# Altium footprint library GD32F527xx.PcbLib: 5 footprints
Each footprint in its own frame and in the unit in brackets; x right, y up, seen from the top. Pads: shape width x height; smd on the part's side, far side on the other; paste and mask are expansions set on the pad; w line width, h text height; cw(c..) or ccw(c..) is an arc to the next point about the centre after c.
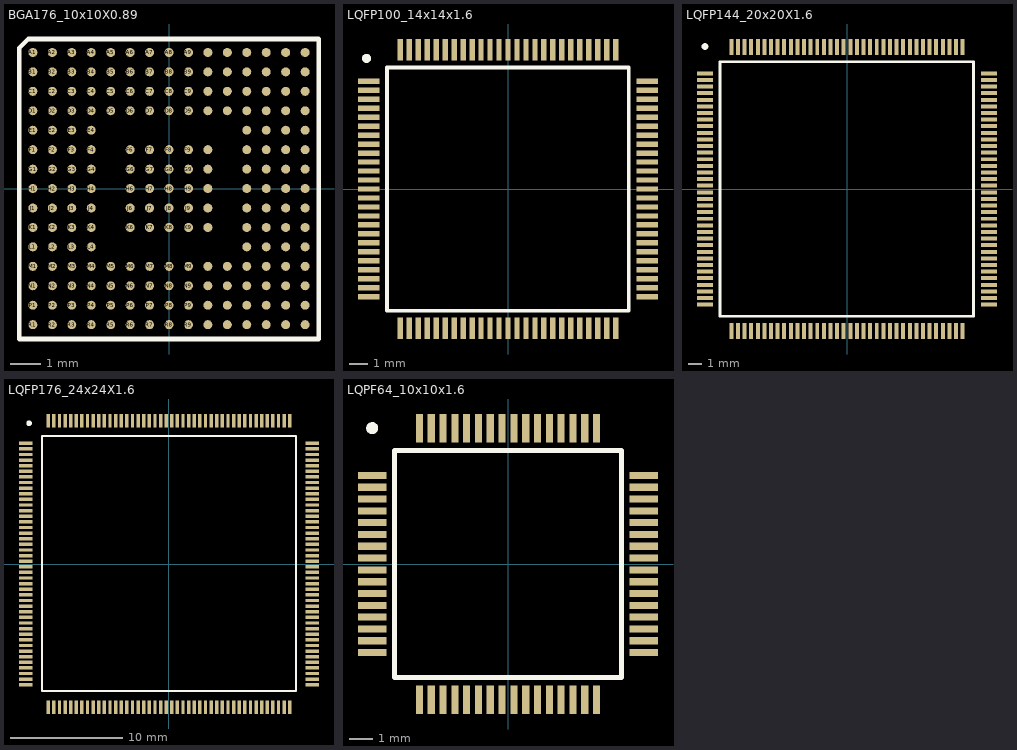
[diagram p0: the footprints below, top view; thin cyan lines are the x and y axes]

## BGA176_10x10X0.89 [mm]
pads (201):
  round 0.3 smd mask+0.05: A1(-4.55,4.55) A2(-3.9,4.55) A3(-3.25,4.55) A4(-2.6,4.55) A5(-1.95,4.55) A6(-1.3,4.55) A7(-0.65,4.55) A8(0,4.55) A9(0.65,4.55) A10(1.3,4.55) A11(1.95,4.55) A12(2.6,4.55) A13(3.25,4.55) A14(3.9,4.55) A15(4.55,4.55) B1(-4.55,3.9) B2(-3.9,3.9) B3(-3.25,3.9) B4(-2.6,3.9) B5(-1.95,3.9) B6(-1.3,3.9) B7(-0.65,3.9) B8(0,3.9) B9(0.65,3.9) B10(1.3,3.9) B11(1.95,3.9) B12(2.6,3.9) B13(3.25,3.9) B14(3.9,3.9) B15(4.55,3.9) C1(-4.55,3.25) C2(-3.9,3.25) C3(-3.25,3.25) C4(-2.6,3.25) C5(-1.95,3.25) C6(-1.3,3.25) C7(-0.65,3.25) C8(0,3.25) C9(0.65,3.25) C10(1.3,3.25) C11(1.95,3.25) C12(2.6,3.25) C13(3.25,3.25) C14(3.9,3.25) C15(4.55,3.25) D1(-4.55,2.6) D2(-3.9,2.6) D3(-3.25,2.6) D4(-2.6,2.6) D5(-1.95,2.6) D6(-1.3,2.6) D7(-0.65,2.6) D8(0,2.6) D9(0.65,2.6) D10(1.3,2.6) D11(1.95,2.6) D12(2.6,2.6) D13(3.25,2.6) D14(3.9,2.6) D15(4.55,2.6) E1(-4.55,1.95) E2(-3.9,1.95) E3(-3.25,1.95) E4(-2.6,1.95) E12(2.6,1.95) E13(3.25,1.95) E14(3.9,1.95) E15(4.55,1.95) F1(-4.55,1.3) F2(-3.9,1.3) F3(-3.25,1.3) F4(-2.6,1.3) F6(-1.3,1.3) F7(-0.65,1.3) F8(0,1.3) F9(0.65,1.3) F10(1.3,1.3) F12(2.6,1.3) F13(3.25,1.3) F14(3.9,1.3) F15(4.55,1.3) G1(-4.55,0.65) G2(-3.9,0.65) G3(-3.25,0.65) G4(-2.6,0.65) G6(-1.3,0.65) G7(-0.65,0.65) G8(0,0.65) G9(0.65,0.65) G10(1.3,0.65) G12(2.6,0.65) G13(3.25,0.65) G14(3.9,0.65) G15(4.55,0.65) H1(-4.55,0) H2(-3.9,0) H3(-3.25,0) H4(-2.6,0) H6(-1.3,0) H7(-0.65,0) H8(0,0) H9(0.65,0) H10(1.3,0) H12(2.6,0) H13(3.25,0) H14(3.9,0) H15(4.55,0) J1(-4.55,-0.65) J2(-3.9,-0.65) J3(-3.25,-0.65) J4(-2.6,-0.65) J6(-1.3,-0.65) J7(-0.65,-0.65) J8(0,-0.65) J9(0.65,-0.65) J10(1.3,-0.65) J12(2.6,-0.65) J13(3.25,-0.65) J14(3.9,-0.65) J15(4.55,-0.65) K1(-4.55,-1.3) K2(-3.9,-1.3) K3(-3.25,-1.3) K4(-2.6,-1.3) K6(-1.3,-1.3) K7(-0.65,-1.3) K8(0,-1.3) K9(0.65,-1.3) K10(1.3,-1.3) K12(2.6,-1.3) K13(3.25,-1.3) K14(3.9,-1.3) K15(4.55,-1.3) L1(-4.55,-1.95) L2(-3.9,-1.95) L3(-3.25,-1.95) L4(-2.6,-1.95) L12(2.6,-1.95) L13(3.25,-1.95) L14(3.9,-1.95) L15(4.55,-1.95) M1(-4.55,-2.6) M2(-3.9,-2.6) M3(-3.25,-2.6) M4(-2.6,-2.6) M5(-1.95,-2.6) M6(-1.3,-2.6) M7(-0.65,-2.6) M8(0,-2.6) M9(0.65,-2.6) M10(1.3,-2.6) M11(1.95,-2.6) M12(2.6,-2.6) M13(3.25,-2.6) M14(3.9,-2.6) M15(4.55,-2.6) N1(-4.55,-3.25) N2(-3.9,-3.25) N3(-3.25,-3.25) N4(-2.6,-3.25) N5(-1.95,-3.25) N6(-1.3,-3.25) N7(-0.65,-3.25) N8(0,-3.25) N9(0.65,-3.25) N10(1.3,-3.25) N11(1.95,-3.25) N12(2.6,-3.25) N13(3.25,-3.25) N14(3.9,-3.25) N15(4.55,-3.25) P1(-4.55,-3.9) P2(-3.9,-3.9) P3(-3.25,-3.9) P4(-2.6,-3.9) P5(-1.95,-3.9) P6(-1.3,-3.9) P7(-0.65,-3.9) P8(0,-3.9) P9(0.65,-3.9) P10(1.3,-3.9) P11(1.95,-3.9) P12(2.6,-3.9) P13(3.25,-3.9) P14(3.9,-3.9) P15(4.55,-3.9) R1(-4.55,-4.55) R2(-3.9,-4.55) R3(-3.25,-4.55) R4(-2.6,-4.55) R5(-1.95,-4.55) R6(-1.3,-4.55) R7(-0.65,-4.55) R8(0,-4.55) R9(0.65,-4.55) R10(1.3,-4.55) R11(1.95,-4.55) R12(2.6,-4.55) R13(3.25,-4.55) R14(3.9,-4.55) R15(4.55,-4.55)
Top Overlay:
  lines w0.152: -5.004,-5.029 5.004,-5.029 5.004,5 -4.703,5 -5.004,4.699 -5.004,-5.029
3D body "BGA176C65P15X15_1000X1000X89.step": height 0.89, standoff 0, extent -5,-5 5,5

## LQFP100_14x14x1.6 [mm]
pads (100):
  rect 1.2x0.3 smd: 1(-7.75,6) 2(-7.75,5.5) 3(-7.75,5) 4(-7.75,4.5) 5(-7.75,4) 6(-7.75,3.5) 7(-7.75,3) 8(-7.75,2.5) 9(-7.75,2) 10(-7.75,1.5) 11(-7.75,1) 12(-7.75,0.5) 13(-7.75,0) 14(-7.75,-0.5) 15(-7.75,-1) 16(-7.75,-1.5) 17(-7.75,-2) 18(-7.75,-2.5) 19(-7.75,-3) 20(-7.75,-3.5) 21(-7.75,-4) 22(-7.75,-4.5) 23(-7.75,-5) 24(-7.75,-5.5) 25(-7.75,-6) 51(7.75,-6) 52(7.75,-5.5) 53(7.75,-5) 54(7.75,-4.5) 55(7.75,-4) 56(7.75,-3.5) 57(7.75,-3) 58(7.75,-2.5) 59(7.75,-2) 60(7.75,-1.5) 61(7.75,-1) 62(7.75,-0.5) 63(7.75,0) 64(7.75,0.5) 65(7.75,1) 66(7.75,1.5) 67(7.75,2) 68(7.75,2.5) 69(7.75,3) 70(7.75,3.5) 71(7.75,4) 72(7.75,4.5) 73(7.75,5) 74(7.75,5.5) 75(7.75,6)
  rect 0.3x1.2 smd: 26(-6,-7.75) 27(-5.5,-7.75) 28(-5,-7.75) 29(-4.5,-7.75) 30(-4,-7.75) 31(-3.5,-7.75) 32(-3,-7.75) 33(-2.5,-7.75) 34(-2,-7.75) 35(-1.5,-7.75) 36(-1,-7.75) 37(-0.5,-7.75) 38(0,-7.75) 39(0.5,-7.75) 40(1,-7.75) 41(1.5,-7.75) 42(2,-7.75) 43(2.5,-7.75) 44(3,-7.75) 45(3.5,-7.75) 46(4,-7.75) 47(4.5,-7.75) 48(5,-7.75) 49(5.5,-7.75) 50(6,-7.75) 76(6,7.75) 77(5.5,7.75) 78(5,7.75) 79(4.5,7.75) 80(4,7.75) 81(3.5,7.75) 82(3,7.75) 83(2.5,7.75) 84(2,7.75) 85(1.5,7.75) 86(1,7.75) 87(0.5,7.75) 88(0,7.75) 89(-0.5,7.75) 90(-1,7.75) 91(-1.5,7.75) 92(-2,7.75) 93(-2.5,7.75) 94(-3,7.75) 95(-3.5,7.75) 96(-4,7.75) 97(-4.5,7.75) 98(-5,7.75) 99(-5.5,7.75) 100(-6,7.75)
Top Overlay:
  circle w0.254: c-7.877,7.27 r0.127
  lines w0.203: -6.734,-6.782 -6.734,6.762 6.728,6.762 6.728,-6.782 -6.734,-6.782
3D body "TSQFP50P1600X1600X160-100N.step": height 1.6, standoff 0, extent -8,-8 8,8

## LQFP144_20x20X1.6 [mm]
pads (144):
  rect 1.2x0.3 smd: 1(-10.75,8.75) 2(-10.75,8.25) 3(-10.75,7.75) 4(-10.75,7.25) 5(-10.75,6.75) 6(-10.75,6.25) 7(-10.75,5.75) 8(-10.75,5.25) 9(-10.75,4.75) 10(-10.75,4.25) 11(-10.75,3.75) 12(-10.75,3.25) 13(-10.75,2.75) 14(-10.75,2.25) 15(-10.75,1.75) 16(-10.75,1.25) 17(-10.75,0.75) 18(-10.75,0.25) 19(-10.75,-0.25) 20(-10.75,-0.75) 21(-10.75,-1.25) 22(-10.75,-1.75) 23(-10.75,-2.25) 24(-10.75,-2.75) 25(-10.75,-3.25) 26(-10.75,-3.75) 27(-10.75,-4.25) 28(-10.75,-4.75) 29(-10.75,-5.25) 30(-10.75,-5.75) 31(-10.75,-6.25) 32(-10.75,-6.75) 33(-10.75,-7.25) 34(-10.75,-7.75) 35(-10.75,-8.25) 36(-10.75,-8.75) 73(10.75,-8.75) 74(10.75,-8.25) 75(10.75,-7.75) 76(10.75,-7.25) 77(10.75,-6.75) 78(10.75,-6.25) 79(10.75,-5.75) 80(10.75,-5.25) 81(10.75,-4.75) 82(10.75,-4.25) 83(10.75,-3.75) 84(10.75,-3.25) 85(10.75,-2.75) 86(10.75,-2.25) 87(10.75,-1.75) 88(10.75,-1.25) 89(10.75,-0.75) 90(10.75,-0.25) 91(10.75,0.25) 92(10.75,0.75) 93(10.75,1.25) 94(10.75,1.75) 95(10.75,2.25) 96(10.75,2.75) 97(10.75,3.25) 98(10.75,3.75) 99(10.75,4.25) 100(10.75,4.75) 101(10.75,5.25) 102(10.75,5.75) 103(10.75,6.25) 104(10.75,6.75) 105(10.75,7.25) 106(10.75,7.75) 107(10.75,8.25) 108(10.75,8.75)
  rect 0.3x1.2 smd: 37(-8.75,-10.75) 38(-8.25,-10.75) 39(-7.75,-10.75) 40(-7.25,-10.75) 41(-6.75,-10.75) 42(-6.25,-10.75) 43(-5.75,-10.75) 44(-5.25,-10.75) 45(-4.75,-10.75) 46(-4.25,-10.75) 47(-3.75,-10.75) 48(-3.25,-10.75) 49(-2.75,-10.75) 50(-2.25,-10.75) 51(-1.75,-10.75) 52(-1.25,-10.75) 53(-0.75,-10.75) 54(-0.25,-10.75) 55(0.25,-10.75) 56(0.75,-10.75) 57(1.25,-10.75) 58(1.75,-10.75) 59(2.25,-10.75) 60(2.75,-10.75) 61(3.25,-10.75) 62(3.75,-10.75) 63(4.25,-10.75) 64(4.75,-10.75) 65(5.25,-10.75) 66(5.75,-10.75) 67(6.25,-10.75) 68(6.75,-10.75) 69(7.25,-10.75) 70(7.75,-10.75) 71(8.25,-10.75) 72(8.75,-10.75) 109(8.75,10.75) 110(8.25,10.75) 111(7.75,10.75) 112(7.25,10.75) 113(6.75,10.75) 114(6.25,10.75) 115(5.75,10.75) 116(5.25,10.75) 117(4.75,10.75) 118(4.25,10.75) 119(3.75,10.75) 120(3.25,10.75) 121(2.75,10.75) 122(2.25,10.75) 123(1.75,10.75) 124(1.25,10.75) 125(0.75,10.75) 126(0.25,10.75) 127(-0.25,10.75) 128(-0.75,10.75) 129(-1.25,10.75) 130(-1.75,10.75) 131(-2.25,10.75) 132(-2.75,10.75) 133(-3.25,10.75) 134(-3.75,10.75) 135(-4.25,10.75) 136(-4.75,10.75) 137(-5.25,10.75) 138(-5.75,10.75) 139(-6.25,10.75) 140(-6.75,10.75) 141(-7.25,10.75) 142(-7.75,10.75) 143(-8.25,10.75) 144(-8.75,10.75)
Top Overlay:
  circle w0.254: c-10.75,10.782 r0.127
  lines w0.203: -9.607,-9.627 9.57,-9.627 9.57,9.639 -9.607,9.639 -9.607,-9.627
3D body "TSQFP50P2200X2200X160-144N.step": height 1.6, standoff 0, extent -11,-11 11,11

## LQFP176_24x24X1.6 [mm]
pads (176):
  rect 1.2x0.3 smd: 1(-12.75,10.75) 2(-12.75,10.25) 3(-12.75,9.75) 4(-12.75,9.25) 5(-12.75,8.75) 6(-12.75,8.25) 7(-12.75,7.75) 8(-12.75,7.25) 9(-12.75,6.75) 10(-12.75,6.25) 11(-12.75,5.75) 12(-12.75,5.25) 13(-12.75,4.75) 14(-12.75,4.25) 15(-12.75,3.75) 16(-12.75,3.25) 17(-12.75,2.75) 18(-12.75,2.25) 19(-12.75,1.75) 20(-12.75,1.25) 21(-12.75,0.75) 22(-12.75,0.25) 23(-12.75,-0.25) 24(-12.75,-0.75) 25(-12.75,-1.25) 26(-12.75,-1.75) 27(-12.75,-2.25) 28(-12.75,-2.75) 29(-12.75,-3.25) 30(-12.75,-3.75) 31(-12.75,-4.25) 32(-12.75,-4.75) 33(-12.75,-5.25) 34(-12.75,-5.75) 35(-12.75,-6.25) 36(-12.75,-6.75) 37(-12.75,-7.25) 38(-12.75,-7.75) 39(-12.75,-8.25) 40(-12.75,-8.75) 41(-12.75,-9.25) 42(-12.75,-9.75) 43(-12.75,-10.25) 44(-12.75,-10.75) 89(12.75,-10.75) 90(12.75,-10.25) 91(12.75,-9.75) 92(12.75,-9.25) 93(12.75,-8.75) 94(12.75,-8.25) 95(12.75,-7.75) 96(12.75,-7.25) 97(12.75,-6.75) 98(12.75,-6.25) 99(12.75,-5.75) 100(12.75,-5.25) 101(12.75,-4.75) 102(12.75,-4.25) 103(12.75,-3.75) 104(12.75,-3.25) 105(12.75,-2.75) 106(12.75,-2.25) 107(12.75,-1.75) 108(12.75,-1.25) 109(12.75,-0.75) 110(12.75,-0.25) 111(12.75,0.25) 112(12.75,0.75) 113(12.75,1.25) 114(12.75,1.75) 115(12.75,2.25) 116(12.75,2.75) 117(12.75,3.25) 118(12.75,3.75) 119(12.75,4.25) 120(12.75,4.75) 121(12.75,5.25) 122(12.75,5.75) 123(12.75,6.25) 124(12.75,6.75) 125(12.75,7.25) 126(12.75,7.75) 127(12.75,8.25) 128(12.75,8.75) 129(12.75,9.25) 130(12.75,9.75) 131(12.75,10.25) 132(12.75,10.75)
  rect 0.3x1.2 smd: 45(-10.75,-12.75) 46(-10.25,-12.75) 47(-9.75,-12.75) 48(-9.25,-12.75) 49(-8.75,-12.75) 50(-8.25,-12.75) 51(-7.75,-12.75) 52(-7.25,-12.75) 53(-6.75,-12.75) 54(-6.25,-12.75) 55(-5.75,-12.75) 56(-5.25,-12.75) 57(-4.75,-12.75) 58(-4.25,-12.75) 59(-3.75,-12.75) 60(-3.25,-12.75) 61(-2.75,-12.75) 62(-2.25,-12.75) 63(-1.75,-12.75) 64(-1.25,-12.75) 65(-0.75,-12.75) 66(-0.25,-12.75) 67(0.25,-12.75) 68(0.75,-12.75) 69(1.25,-12.75) 70(1.75,-12.75) 71(2.25,-12.75) 72(2.75,-12.75) 73(3.25,-12.75) 74(3.75,-12.75) 75(4.25,-12.75) 76(4.75,-12.75) 77(5.25,-12.75) 78(5.75,-12.75) 79(6.25,-12.75) 80(6.75,-12.75) 81(7.25,-12.75) 82(7.75,-12.75) 83(8.25,-12.75) 84(8.75,-12.75) 85(9.25,-12.75) 86(9.75,-12.75) 87(10.25,-12.75) 88(10.75,-12.75) 133(10.75,12.75) 134(10.25,12.75) 135(9.75,12.75) 136(9.25,12.75) 137(8.75,12.75) 138(8.25,12.75) 139(7.75,12.75) 140(7.25,12.75) 141(6.75,12.75) 142(6.25,12.75) 143(5.75,12.75) 144(5.25,12.75) 145(4.75,12.75) 146(4.25,12.75) 147(3.75,12.75) 148(3.25,12.75) 149(2.75,12.75) 150(2.25,12.75) 151(1.75,12.75) 152(1.25,12.75) 153(0.75,12.75) 154(0.25,12.75) 155(-0.25,12.75) 156(-0.75,12.75) 157(-1.25,12.75) 158(-1.75,12.75) 159(-2.25,12.75) 160(-2.75,12.75) 161(-3.25,12.75) 162(-3.75,12.75) 163(-4.25,12.75) 164(-4.75,12.75) 165(-5.25,12.75) 166(-5.75,12.75) 167(-6.25,12.75) 168(-6.75,12.75) 169(-7.25,12.75) 170(-7.75,12.75) 171(-8.25,12.75) 172(-8.75,12.75) 173(-9.25,12.75) 174(-9.75,12.75) 175(-10.25,12.75) 176(-10.75,12.75)
Top Overlay:
  circle w0.254: c-12.446,12.528 r0.127
  lines w0.203: -11.303,-11.303 -11.303,11.385 11.303,11.385 11.303,-11.303 -11.303,-11.303
3D body "TSQFP50P2600X2600X160-176N.step": height 1.6, standoff 0, extent -13,-13 13,13

## LQPF64_10x10x1.6 [mm]
pads (64):
  rect 1.2x0.3 smd: 1(-5.75,3.75) 2(-5.75,3.25) 3(-5.75,2.75) 4(-5.75,2.25) 5(-5.75,1.75) 6(-5.75,1.25) 7(-5.75,0.75) 8(-5.75,0.25) 9(-5.75,-0.25) 10(-5.75,-0.75) 11(-5.75,-1.25) 12(-5.75,-1.75) 13(-5.75,-2.25) 14(-5.75,-2.75) 15(-5.75,-3.25) 16(-5.75,-3.75) 33(5.75,-3.75) 34(5.75,-3.25) 35(5.75,-2.75) 36(5.75,-2.25) 37(5.75,-1.75) 38(5.75,-1.25) 39(5.75,-0.75) 40(5.75,-0.25) 41(5.75,0.25) 42(5.75,0.75) 43(5.75,1.25) 44(5.75,1.75) 45(5.75,2.25) 46(5.75,2.75) 47(5.75,3.25) 48(5.75,3.75)
  rect 0.3x1.2 smd: 17(-3.75,-5.75) 18(-3.25,-5.75) 19(-2.75,-5.75) 20(-2.25,-5.75) 21(-1.75,-5.75) 22(-1.25,-5.75) 23(-0.75,-5.75) 24(-0.25,-5.75) 25(0.25,-5.75) 26(0.75,-5.75) 27(1.25,-5.75) 28(1.75,-5.75) 29(2.25,-5.75) 30(2.75,-5.75) 31(3.25,-5.75) 32(3.75,-5.75) 49(3.75,5.75) 50(3.25,5.75) 51(2.75,5.75) 52(2.25,5.75) 53(1.75,5.75) 54(1.25,5.75) 55(0.75,5.75) 56(0.25,5.75) 57(-0.25,5.75) 58(-0.75,5.75) 59(-1.25,5.75) 60(-1.75,5.75) 61(-2.25,5.75) 62(-2.75,5.75) 63(-3.25,5.75) 64(-3.75,5.75)
Top Overlay:
  circle w0.254: c-5.75,5.75 r0.127
  lines w0.203: -4.801,-4.801 4.801,-4.801 4.801,4.801 -4.801,4.801 -4.801,-4.801
3D body "TSQFP50P1200X1200X160-64N.step": height 1.6, standoff 0, extent -6,-6 6,6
